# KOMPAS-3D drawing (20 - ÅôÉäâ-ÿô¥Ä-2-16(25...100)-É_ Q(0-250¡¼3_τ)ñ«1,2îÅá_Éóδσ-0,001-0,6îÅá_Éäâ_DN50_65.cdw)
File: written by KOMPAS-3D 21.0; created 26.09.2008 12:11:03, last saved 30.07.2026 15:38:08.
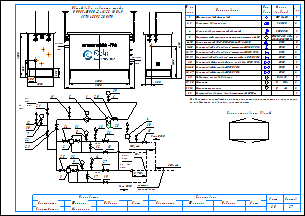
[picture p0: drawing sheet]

Sheets 1-2: A3, landscape

Document properties: Наименование: Макро:21; Автор: RaskoAdmin; Форматы листов документа: 2xA3; Полное имя файла: \\ur38nt01\Departments\КТО\КБ ПУРДГ\Заявки\Прайс-лист на типовые шкафы ГРПШ\ПУРДГ_стандарт_30_04_2026\ПУРДГ с РДГ(Н, В)\ПУРДГ-ШУЭО-2-16(25...100)-Р_ Q(0-250нм3_ч)до1,2МПа_Рвых-0,001-0,6МПа_РДГ_DN50_65.cdw

Title block, sheet 1: Наименование: Пункт учета газа / ПУГ-Ш-400-Р / ЛГТИ.485922.001ТУ; designation: ЛГТИ.03.4411141; sheet number: 1; Количество листов документа: 2; organisation: ООО "ЭЛЬСТЕР Газэлектроника"; Форматы листов документа: A3; stored path: C:\Рабочие документы\Компас\ПУГ\Схема.cdw; Разработал: Устинов; Проверил: Кошкин; Утвердил: Кошкин
Title block, sheet 2: sheet number: 2; stored path: D:\Рабочие документы\Заявки\ПУРДГ\ПУРДГ-ШУЭО-2-100-Р 4411220.cdw; designation, second copy: ЛГТИ.03.4411141-

Views: Вид 1, Вид 2
Referenced files: wcvoit.frw
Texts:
  Normal
  № на
  схеме
  Усл.
  обозн.
  Марка
  (модель)
  Кол.
  Фильтр газовый фланцевый
  ФГ 16-50
  Регулятор давления газа
  РДГ-50
  Клапан предохранительный сбросной
  КПС DN20
  Измерительный комплекс с ротационным счетчиком Ду50
  СГ-ЭК-Р-(0,2...2,0)-
  Кран кнопочный VE-РАСКО-НЗ-1,6-G1/2-М20
  DN15
  Кран шаровой "под приварку" штуцерный DN20 PN16
  DN20
  Кран шаровой "под приварку" штуцерный DN15 PN16
  Кран шаровой "под приварку" штуцерный п/п DN20 PN16
  Кран шаровой фланцевый с мех. приводом DN50 PN16
  Кран шаровой фланцевый DN50 PN16
  Кран шаровой фланцевый DN65 PN16
  DN50
  DN65
  Индикатор перепада давления
  Манометр
  Манометр-напоромер
  Электрообогреватель взрывозащищенный 600Вт
  Delta 15
  0...     МПа
  0...     кПа
  Общий вид и габариты шкафа
  ПУРДГ-ШУЭО-2-16(25...100)-Р
  Выход газа
  Вход газа
  logo-rasko-ge.png
  DN 1
  местное
  сопротивление
  Римп DN20
  Выход
  газа
  Р=     кПа
  Вход
  Р=       МПа
  PDI
  Схема открывания дверей
  Предприятие изготовитель может заменять комплектующие на аналогичные,
  не ухудшающие заявленных характеристик.
  Должность
  Конструктор
  Фамилия
  Подпись
  Дата
  Согласовано
  Максимкин
  Лист
  Листов
  POLYLINE_STYLE_0.18_RGB_0_0_0
  POLYLINE_STYLE_0.50_RGB_0_0_0
  POLYLINE_STYLE_0.34_RGB_0_0_0
  PHANTOM_RGB_0_0_0_SC_1_THICK_0.18
  K5LT_THIN_RGB_0_0_0_THICK_0.18
  K5LT32769_RGB_0_0_0_THICK_0.18
  K5LT12_RGB_0_0_0_SC_1_THICK_0.18
  K5LT_DASHED_RGB_0_0_0_SC_1_THICK_0.18
  ACISOTGL_RGB_0_0_0_SC_0.8_THICK_0.25
  CONTINUOUS_RGB_0_127_31_THICK_0.3
  CONTINUOUS_RGB_0_0_255_THICK_0.35
  CONTINUOUS_RGB_255_0_0_THICK_0.35
  POLYLINE_STYLE_0.25_RGB_0_0_0
  CONTINUOUS_RGB_0_0_0_THICK_0.5
  POLYLINE_STYLE_0.35_RGB_0_0_255
  CONTINUOUS_RGB_0_0_0_THICK_0.4
  CONTINUOUS_RGB_0_0_0_THICK_0.35
  НЕВИДИМАЯ_RGB_0_0_0_SC_0.3_THICK_0.25
  СONTINUOUS_RGB_0_0_0_THICK_0.25
  ОСЕВАЯ2_RGB_248_153_30_SC_0.3_THICK_0.25
  Без оформления
Dimensions and other numbers on the sheet: 1; 2, 3; 2; 4; 5; 6-10; 11-15; 16, 17; 18, 19; 20; 21-25; 26, 27; 28; 29, 30; 31, 32; 33; 1500; 250; 300; 1050; 550; 305; 2500; 4130; 2000; 2800; 5,,,7DN 1; 7; 30; 12; 21; 22; 23; 11; 6; 29; 24; 31; 8; 13; 26; 18; 10; 15; 25; 32; 9; 3; 14; 27; 19; 16; 17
